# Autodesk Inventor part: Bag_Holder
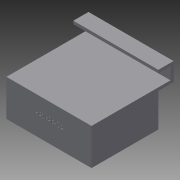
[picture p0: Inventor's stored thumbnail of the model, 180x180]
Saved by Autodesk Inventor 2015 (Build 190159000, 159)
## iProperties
Created: 2017-04
Part Number: Bag_Holder
Material: Generisch
Document SubType Name: Modeling
Designer: Andreas
Density: 1 g/cm^3
Appearance: Vorgabe
Author: Andreas
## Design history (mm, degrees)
sketch "Skizze1"
  geometry: L1 (0, 0)-(140, 0); L2 (140, 0)-(140, 110); L3 (140, 110)-(0, 110); L4 (0, 110)-(0, 0)
  constraints: 8 end point, 2 perpendicular, 1 horizontal
  dimensions: "d0" = 140 distance of L1.start L1.end; "d1" = 110 distance of L1.end L2.end; "d2" = 140 distance of L2.end L3.end
extrude "Extrusion1" new body sketch "Skizze1" distance "d3" = 60; taper "d4" = 0 deg
sketch "Skizze2"
  geometry: L1 (140, 0)-(0, 0) reference; L2 (0, 0)-(0, -60) reference; L3 (140, -60)-(0, -60) reference; L4 (140, 0)-(140, -60) reference; L5 (5, -55)-(5, -5); L6 (5, -5)-(135, -5); L7 (135, -5)-(135, -55); L8 (135, -55)-(5, -55); 1 further point
  constraints: 8 end point, 3 other
  dimensions: "d5" = 5 distance between parallel lines of L2 L5
extrude "Extrusion2" cut sketch "Skizze2" distance "d6" = 105; taper "d7" = 0 deg
sketch "Skizze5"
  geometry: L1 (0, 110)-(140, 110); L2 (140, 0)-(140, 110) reference; L3 (140, 110)-(140, 135); L4 (140, 135)-(0, 135); L5 (0, 135)-(0, 110); L6 (0, 110)-(0, 0) reference
  constraints: 8 end point, 3 perpendicular, 1 collinear
  dimensions: "d12" = 25 distance of L1.end L3.end; "d13" = 140 distance of L3.end L4.end; "d14" = 90 deg angle of L4 L3 (derived)
extrude "Extrusion5" join sketch "Skizze5" distance "d15" = 5; taper "d16" = 0 deg
sketch "Skizze6"
  geometry: L1 (60, 135)-(85, 135); L2 (85, 135)-(85, 110); L3 (85, 110)-(80, 110); L4 (80, 110)-(80, 130); L5 (80, 130)-(60, 130); L6 (60, 0)-(60, 135) reference; 1 further point
  constraints: 10 end point, 3 perpendicular, 1 horizontal, 1 point on line
  dimensions: "d17" = 25 distance of L1.start L1.end; "d18" = 25 distance of L1.end L2.end; "d19" = 5 distance of L2.end L3.end; "d20" = 20 distance of L3.end L4.end; "d21" = 20 distance of L4.end L5.end
extrude "Extrusion6" join sketch "Skizze6" distance "d22" = 140; taper "d23" = 0 deg
sketch "Skizze7"
  geometry: L1 (-137.313, 110)-(2.687, 110); L2 (0, 110)-(0, 69.77); L3 (0, 69.77)-(-140, 69.77); L4 (-140, 69.77)-(-140, 110); L5 (-105.842, 83.139)-(-107.104, 77.52); L6 (-112.083, 56.015)-(-113.352, 50.367); L7 (-90.803, 57.74)-(-97.488, 57.74); L8 (-97.488, 57.74)-(-93.441, 75.789); L9 (-93.441, 75.789)-(-85.241, 75.789); L10 (-85.241, 75.789)-(-80.374, 65.41); L11 (-80.374, 65.41)-(-78.047, 75.789); L12 (-78.047, 75.789)-(-71.352, 75.789); L13 (-71.352, 75.789)-(-75.399, 57.74); L14 (-75.399, 57.74)-(-82.426, 57.74); L15 (-82.426, 57.74)-(-88.137, 69.595); L16 (-88.137, 69.595)-(-90.803, 57.74); L17 (-63.137, 71.121)-(-66.14, 57.74); L18 (-66.14, 57.74)-(-73.145, 57.74); L19 (0, 110)-(-140, 110) reference; L20 (-73.145, 57.74)-(-69.094, 75.789); L21 (-69.094, 75.789)-(-60.412, 75.789); L22 (-55.495, 63.512)-(-52.866, 60.091); L23 (-52.866, 60.091)-(-46.62, 68.921); L24 (-44.024, 72.592)-(-46.62, 68.921); L25 (-39.608, 75.725)-(-27.28, 75.725); L26 (-27.28, 75.725)-(-31.3, 57.828); L27 (-31.3, 57.828)-(-38.333, 57.828); L28 (-38.333, 57.828)-(-37.565, 60.915); L29 (-37.565, 60.915)-(-45, 60.99); L30 (-45, 60.99)-(-47.076, 57.828); L31 (-47.076, 57.828)-(-55.28, 57.828); L32 (-63.137, 71.121)-(-60.099, 71.121); L33 (-58.075, 71.121)-(-60.099, 71.121); L34 (-63.381, 67.065)-(-57.341, 67.065); L35 (-35.609, 71.121)-(-36.808, 65.41); L36 (-36.808, 65.41)-(-42.096, 65.41); L37 (-42.096, 65.41)-(-39.407, 69.504); L38 (-25.058, 75.722)-(-29.059, 57.737); L39 (-29.059, 57.737)-(-17.854, 57.737); L40 (-25.058, 75.722)-(-15.922, 75.722); L41 (-17.854, 57.737)-(-13.347, 57.786); L42 (-10.419, 75.722)-(-15.922, 75.722); L43 (-14.218, 71.121)-(-19.118, 71.121); L44 (-19.118, 71.121)-(-21.082, 62.375); L45 (-21.082, 62.375)-(-15.651, 62.375); 116 further points; 1 other entity
  constraints: 82 end point, 10 parallel, 8 horizontal, 7 point on line, 1 collinear, 134 other
extrude "Extrusion7" cut sketch "Skizze7" distance "d72" = 3; taper "d73" = 0 deg
sketch "Skizze8"
  geometry: L1 (92.94, 30.685)-(45.585, 30.685); L2 (45.585, 30.685)-(45.585, 39.666); L3 (45.585, 39.666)-(92.94, 39.666); L4 (92.94, 39.666)-(92.94, 30.685); 1 further point
  constraints: 2 other
extrude "Extrusion8" cut sketch "Skizze8" distance "d74" = 3; taper "d75" = 0 deg
sketch "Skizze3"
  geometry: L1 (-116.179, 82.577)-(-15.781, 82.577); L2 (-15.781, 82.577)-(-15.781, 61.354); L3 (-15.781, 61.354)-(-116.179, 61.354); L4 (-116.179, 61.354)-(-116.179, 82.577); 1 further point
  constraints: 2 other
extrude "Extrusion3" cut sketch "Skizze3" distance "d8" = 1.5; taper "d9" = 0 deg
node "Volumenkörper1"
node "Projizierte Kontur1"
node "Bild2"
